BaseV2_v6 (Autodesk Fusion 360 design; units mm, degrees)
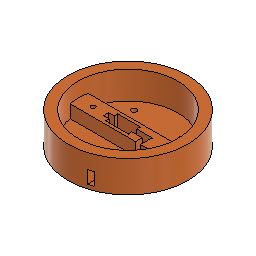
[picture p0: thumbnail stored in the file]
parameter "d25" = 7
parameter "d27" = 7
parameter "d64" = 5.5
sketch "Sketch2" plane through (0, 0, 0) normal (0, 0, 1) x axis (1, 0, 0)
  line L1 (-51.6842, 30.4754) -> (51.6842, 30.4754)
  line L2 (60, 0) -> (-60, 0)
  line L3 (0, 60) -> (0, 0)
  circle C1 centre (0, 0) radius 60
  circle C2 centre (24.2286, 30.4754) radius 2.6
  circle C3 centre (-24.2286, 30.4754) radius 2.6
  circle C4 centre (24.2286, -30.4754) radius 2.6
  circle C5 centre (-24.2286, -30.4754) radius 2.6
  point P1 (0, 0)
  point P2 (0, 0)
  point P3 (51.6842, 30.4754)
  point P4 (-51.6842, 30.4754)
  point P5 (-60, 0)
  point P6 (60, 0)
  point P7 (24.2286, 30.4754)
  point P8 (0, 0)
  point P9 (0, 60)
  coincident P1 P2
  coincident C1 P3
  coincident C1 P4
  horizontal L1
  coincident C1 P5
  coincident C1 P6
  horizontal L2
  coincident L1 P7
  coincident P1 P8
  coincident C1 P9
  perpendicular L2 L3
  symmetric C2 L3 C3
  symmetric L2 C2 C4
  symmetric L2 C3 C5
  dimension "d13" diameter C1 = 120
  dimension "d39" diameter C2 = 5.2
sketch "Sketch1" plane through (0, 0, 0) normal (0, 0, 1) x axis (1, 0, 0)
  line L1 (50, 0) -> (-50, 0)
  line L2 (-5.15, -2.0049) -> (-5.15, 2.3846)
  line L3 (-16.5, -6.1) -> (6.2, -6.1)
  line L4 (-16.5, 6.1) -> (-16.5, -6.1)
  line L5 (6.2, 6.1) -> (-16.5, 6.1)
  line L6 (6.2, -6.1) -> (6.2, 6.1)
  line L7 (-16.5, 6.1) -> (6.2, -6.1)
  line L8 (6.2, 6.1) -> (-16.5, -6.1)
  line L9 (49.1649, 9.1) -> (-49.1649, 9.1)
  line L10 (-49.1649, -9.1) -> (49.1649, -9.1)
  line L11 (49.4157, -7.6217) -> (-49.4157, 7.6217)
  line L12 (-49.4157, -7.6217) -> (49.4157, 7.6217)
  line L13 (0, 9.1) -> (0, -9.1)
  line L14 (-22.05, -2.5) -> (-16.05, -2.5)
  line L15 (-22.05, 2.5) -> (-22.05, -2.5)
  line L16 (-16.05, 2.5) -> (-22.05, 2.5)
  line L17 (-16.05, -2.5) -> (-16.05, 2.5)
  line L18 (-22.05, 2.5) -> (-16.05, -2.5)
  line L19 (-16.05, 2.5) -> (-22.05, -2.5)
  line L20 (5.75, -2.5) -> (11.75, -2.5)
  line L21 (5.75, 2.5) -> (5.75, -2.5)
  line L22 (11.75, 2.5) -> (5.75, 2.5)
  line L23 (11.75, -2.5) -> (11.75, 2.5)
  line L24 (5.75, 2.5) -> (11.75, -2.5)
  line L25 (11.75, 2.5) -> (5.75, -2.5)
  circle C1 centre (0, 0) radius 50
  circle C2 centre (0, 0) radius 2.5
  circle C3 centre (-19.05, 0) radius 1
  circle C4 centre (8.75, 0) radius 1
  circle C5 centre (0, 0) radius 60
  circle C6 centre (35, 0) radius 2.1
  circle C7 centre (-35, 0) radius 2.1
  point P4 (-50, 0)
  point P5 (50, 0)
  point P6 (-19.05, 0)
  point P7 (8.75, 0)
  point P14 (-5.15, 0)
  point P16 (0, 0)
  point P15 (0, 0)
  point P17 (-49.1649, -9.1)
  point P18 (-49.1649, 9.1)
  point P19 (-49.4157, 7.6217)
  point P20 (-49.4157, -7.6217)
  point P21 (49.1649, 9.1)
  point P22 (49.1649, -9.1)
  point P23 (49.4157, -7.6217)
  point P24 (49.4157, 7.6217)
  point P25 (-19.05, 0)
  point P26 (35, 0)
  point P27 (0, -9.1)
  point P28 (0, 9.1)
  point P30 (-19.05, 0)
  point P31 (8.75, 0)
  point P36 (-19.05, 0)
  point P41 (8.75, 0)
  point P2 (0, 0)
  point P12 (-16.5, 6.1)
  point P13 (6.2, 6.1)
  point P11 (-16.5, -6.1)
  point P34 (-22.05, 2.5)
  point P35 (-16.05, 2.5)
  point P33 (-22.05, -2.5)
  point P39 (5.75, 2.5)
  point P40 (11.75, 2.5)
  point P38 (5.75, -2.5)
  concentric C1 C2
  coincident C1 P4
  coincident C1 P5
  horizontal L1
  coincident L1 P6
  coincident L1 P7
  perpendicular L1 L2
  horizontal L3
  perpendicular L3 L4
  parallel L3 L5
  parallel L4 L6
  coincident L7 P14
  coincident L8 P14
  coincident L1 P14
  coincident L2 P14
  concentric C2 C5
  horizontal L9
  parallel L9 L10
  coincident L11 P16
  coincident L12 P16
  coincident P15 P16
  coincident C1 P17
  coincident C1 P18
  coincident C1 P19
  coincident C1 P20
  coincident C1 P21
  coincident C1 P22
  coincident C1 P23
  coincident C1 P24
  coincident P6 P25
  coincident L1 P26
  midpoint L10 P27
  midpoint L9 P28
  symmetric C6 L13 C7
  coincident P6 P30
  coincident P7 P31
  horizontal L14
  perpendicular L14 L15
  parallel L14 L16
  parallel L15 L17
  coincident L18 P36
  coincident L19 P36
  coincident P25 P36
  horizontal L20
  perpendicular L20 L21
  parallel L20 L22
  parallel L21 L23
  coincident L24 P41
  coincident L25 P41
  coincident P31 P41
  dimension "d2" diameter C1 = 100
  dimension "d3" diameter C2 = 5
  dimension "d4" diameter C3 = 2
  dimension "d5" distance P2 P6 = 19.05
  dimension "d6" diameter C4 = 2 (= "d4")
  dimension "d7" distance P2 P7 = 8.75
  dimension "d8" distance P2 L2 = 5.15
  dimension "d9" distance P12 P13 = 22.7
  dimension "d10" distance P11 P12 = 12.2
  dimension "d16" diameter C5 = 120
  dimension "d40" diameter C6 = 4.2
  dimension "d41" distance P2 P26 = 35
  dimension "d66" distance P34 P35 = 6
  dimension "d67" distance P33 P34 = 5
  dimension "d68" distance P39 P40 = 6
  dimension "d69" distance P38 P39 = 5
extrude "Extrude2" new body sketch "Sketch2" profile of C1 C2 C3 C4 C5 against normal blind 4
extrude "Extrude3" add sketch "Sketch1" profile of C1 C5 along normal blind 27.7 (= "30.7 mm - 3 mm")
extrude "Extrude4" add sketch "Sketch1" profile of C1 L3 L4 L5 L6 L9 L10 C6 C7 L14 L15 L16 L20 L22 L23 along normal blind 12.9 (= "15.9 mm - 3 mm")
sketch "Sketch5" plane through (0, 0, 0) normal (0, 1, 0) x axis (1, 0, 0)
extrude "Extrude7" cut of existing geometry blind -4
extrude "Extrude11" cut of existing geometry blind -10
sketch "Sketch9" plane through (0, -2.5, 0) normal (0, 1, 0) x axis (-1, 0, 0)
  line L1 (-6.2, 0) -> (-21.75, 0)
  line L2 (-6.2, 12.9) -> (-6.2, 0)
  line L3 (-21.75, 12.9) -> (-6.2, 12.9)
  line L4 (-21.75, 0) -> (-21.75, 12.9)
  line L5 (-16.75, 12.9) -> (-21.75, 12.9)
  line L6 (-16.75, 0) -> (-16.75, 12.9)
  line L7 (-21.75, 0) -> (-16.75, 0)
  line L8 (-21.75, 12.9) -> (-21.75, 0)
  point P5 (-21.75, 12.9)
  point P6 (-21.75, 12.9)
  point P7 (-16.75, 12.9)
  point P9 (-21.75, 0)
  horizontal L5
  vertical L6
  horizontal L7
  vertical L8
  coincident P5 P6
  dimension "d72" distance P6 P7 = 5
  dimension "d73" distance P6 P9 = 12.9
extrude "Extrude12" cut sketch "Sketch9" profile of L1 L3 L4 L5 L6 L7 L8 to an object
extrude "Extrude13" cut sketch "Sketch1" profile of C3 C4 L4 L6 C6 L14 L15 L16 L20 L22 L23 against normal blind 4
chamfer "Chamfer1" distance 2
